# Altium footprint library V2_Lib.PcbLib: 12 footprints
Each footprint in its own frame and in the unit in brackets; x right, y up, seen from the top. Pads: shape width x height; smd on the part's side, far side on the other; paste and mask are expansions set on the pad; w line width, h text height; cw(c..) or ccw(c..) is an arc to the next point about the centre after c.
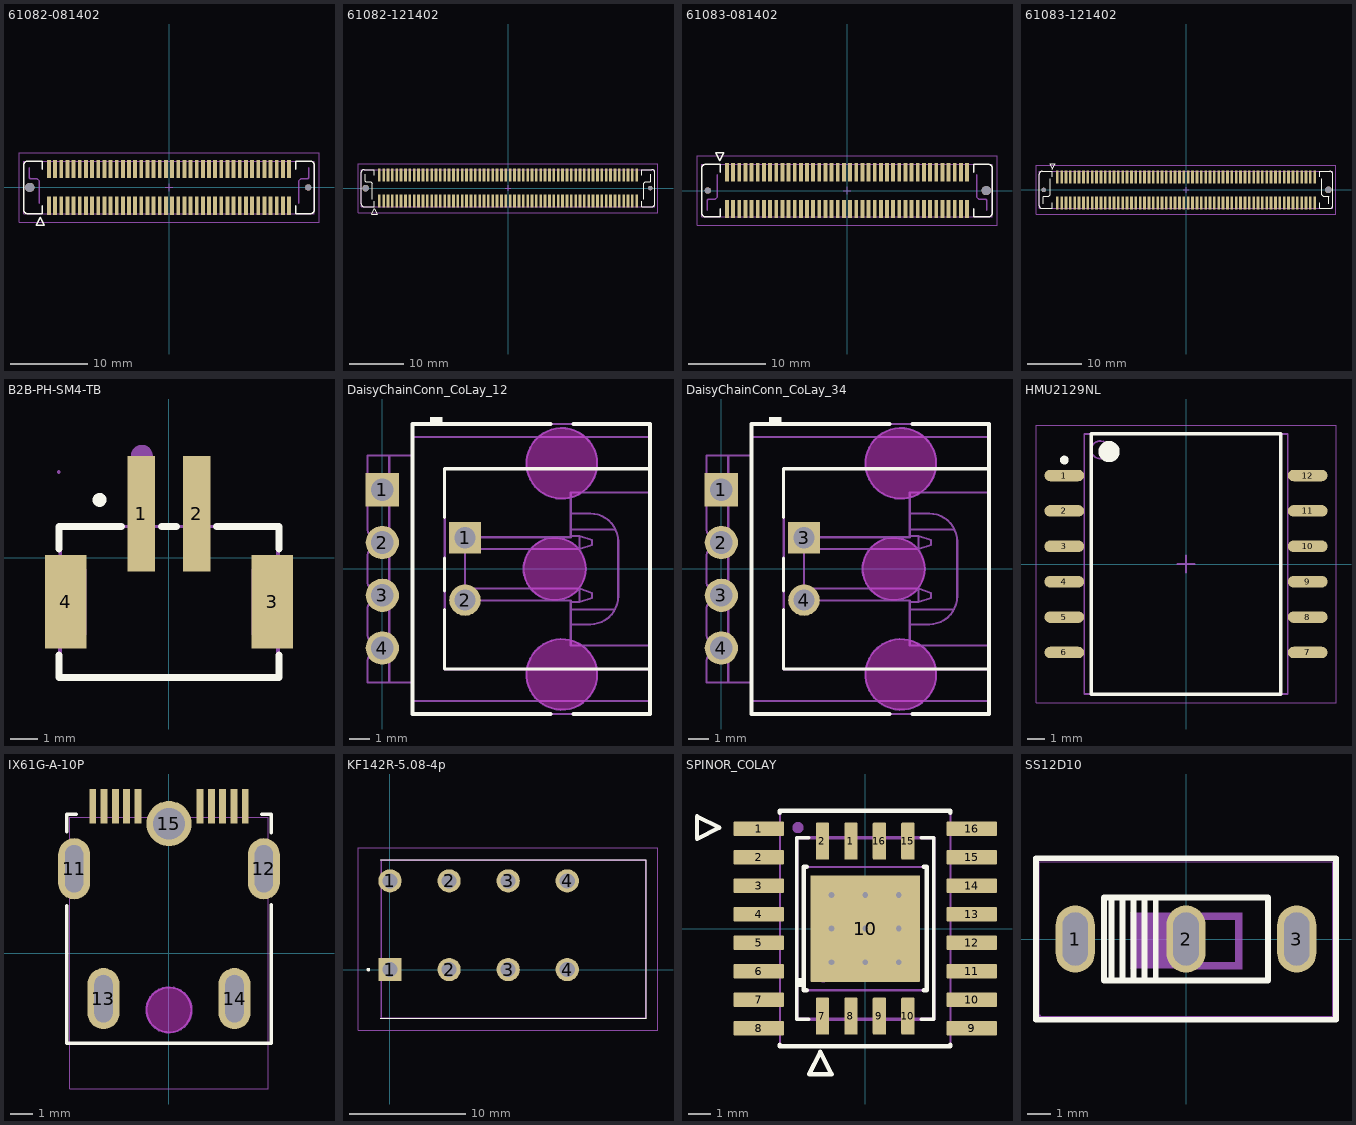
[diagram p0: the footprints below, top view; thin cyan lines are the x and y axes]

## 61082-081402 [mm] "Bergstak 0.8mm Board-to-Board Connector, Receptable, 80 Pos"
height 7.7
pads (82):
  rect 0.5x2.4 smd: 1(-15.6,-2.4) 2(-14.8,-2.4) 3(-14,-2.4) 4(-13.2,-2.4) 5(-12.4,-2.4) 6(-11.6,-2.4) 7(-10.8,-2.4) 8(-10,-2.4) 9(-9.2,-2.4) 10(-8.4,-2.4) 11(-7.6,-2.4) 12(-6.8,-2.4) 13(-6,-2.4) 14(-5.2,-2.4) 15(-4.4,-2.4) 16(-3.6,-2.4) 17(-2.8,-2.4) 18(-2,-2.4) 19(-1.2,-2.4) 20(-0.4,-2.4) 21(0.4,-2.4) 22(1.2,-2.4) 23(2,-2.4) 24(2.8,-2.4) 25(3.6,-2.4) 26(4.4,-2.4) 27(5.2,-2.4) 28(6,-2.4) 29(6.8,-2.4) 30(7.6,-2.4) 31(8.4,-2.4) 32(9.2,-2.4) 33(10,-2.4) 34(10.8,-2.4) 35(11.6,-2.4) 36(12.4,-2.4) 37(13.2,-2.4) 38(14,-2.4) 39(14.8,-2.4) 40(15.6,-2.4) 41(-15.6,2.4) 42(-14.8,2.4) 43(-14,2.4) 44(-13.2,2.4) 45(-12.4,2.4) 46(-11.6,2.4) 47(-10.8,2.4) 48(-10,2.4) 49(-9.2,2.4) 50(-8.4,2.4) 51(-7.6,2.4) 52(-6.8,2.4) 53(-6,2.4) 54(-5.2,2.4) 55(-4.4,2.4) 56(-3.6,2.4) 57(-2.8,2.4) 58(-2,2.4) 59(-1.2,2.4) 60(-0.4,2.4) 61(0.4,2.4) 62(1.2,2.4) 63(2,2.4) 64(2.8,2.4) 65(3.6,2.4) 66(4.4,2.4) 67(5.2,2.4) 68(6,2.4) 69(6.8,2.4) 70(7.6,2.4) 71(8.4,2.4) 72(9.2,2.4) 73(10,2.4) 74(10.8,2.4) 75(11.6,2.4) 76(12.4,2.4) 77(13.2,2.4) 78(14,2.4) 79(14.8,2.4) 80(15.6,2.4)
  round 1.2 hole 1.2: MH1(-18.1,0)
  round 0.8 hole 0.8: MH2(18.1,0)
Top Overlay:
  lines w0.2: -16.5,-2.4 -16.5,-3.4 -18.4,-3.4 cw(c-18.4,-2.9) -18.9,-2.9 -18.9,2.9 cw(c-18.4,2.9) -18.4,3.4 -16.5,3.4 -16.5,2.4 ; 16.5,-2.4 16.5,-3.4 18.4,-3.4 ccw(c18.4,-2.9) 18.9,-2.9 18.9,2.9 ccw(c18.4,2.9) 18.4,3.4 16.5,3.4 16.5,2.4 ; -17.238,-4.905 -16.238,-4.905 -16.738,-3.905 -17.238,-4.905
Mechanical 3:
  lines w0.2: -18.161,2.54 -18.161,1.27 -18.034,1.143 -17.145,1.143 -16.891,0.889 -16.891,-2.032 ; 16.891,-2.032 16.891,0.889 17.145,1.143 18.034,1.143 18.161,1.27 18.161,2.54
Mechanical 5:
  lines w0.1: -18.9,-3.4 -18.9,3.4 18.9,3.4 18.9,-3.4 -18.9,-3.4
Mechanical 15:
  lines w0.05: -19.5,-4.5 -19.5,4.5 19.5,4.5 19.5,-4.5 -19.5,-4.5
  lines w0.1: -0.5,0 0.5,0 ; 0,-0.5 0,0.5
3D body "61082-081402LF--3DModel-STEP-533217.STEP": height 3.7, standoff -0.65, extent -18.9,-3 18.9,3

## 61082-121402 [mm] "Bergstak 0.8mm Board-to-Board Connector, Receptable, 120 Pos, 4.7mm"
height 7.7
pads (122):
  rect 0.5x2.4 smd: 1(-23.6,-2.4) 2(-22.8,-2.4) 3(-22,-2.4) 4(-21.2,-2.4) 5(-20.4,-2.4) 6(-19.6,-2.4) 7(-18.8,-2.4) 8(-18,-2.4) 9(-17.2,-2.4) 10(-16.4,-2.4) 11(-15.6,-2.4) 12(-14.8,-2.4) 13(-14,-2.4) 14(-13.2,-2.4) 15(-12.4,-2.4) 16(-11.6,-2.4) 17(-10.8,-2.4) 18(-10,-2.4) 19(-9.2,-2.4) 20(-8.4,-2.4) 21(-7.6,-2.4) 22(-6.8,-2.4) 23(-6,-2.4) 24(-5.2,-2.4) 25(-4.4,-2.4) 26(-3.6,-2.4) 27(-2.8,-2.4) 28(-2,-2.4) 29(-1.2,-2.4) 30(-0.4,-2.4) 31(0.4,-2.4) 32(1.2,-2.4) 33(2,-2.4) 34(2.8,-2.4) 35(3.6,-2.4) 36(4.4,-2.4) 37(5.2,-2.4) 38(6,-2.4) 39(6.8,-2.4) 40(7.6,-2.4) 41(8.4,-2.4) 42(9.2,-2.4) 43(10,-2.4) 44(10.8,-2.4) 45(11.6,-2.4) 46(12.4,-2.4) 47(13.2,-2.4) 48(14,-2.4) 49(14.8,-2.4) 50(15.6,-2.4) 51(16.4,-2.4) 52(17.2,-2.4) 53(18,-2.4) 54(18.8,-2.4) 55(19.6,-2.4) 56(20.4,-2.4) 57(21.2,-2.4) 58(22,-2.4) 59(22.8,-2.4) 60(23.6,-2.4) 61(-23.6,2.4) 62(-22.8,2.4) 63(-22,2.4) 64(-21.2,2.4) 65(-20.4,2.4) 66(-19.6,2.4) 67(-18.8,2.4) 68(-18,2.4) 69(-17.2,2.4) 70(-16.4,2.4) 71(-15.6,2.4) 72(-14.8,2.4) 73(-14,2.4) 74(-13.2,2.4) 75(-12.4,2.4) 76(-11.6,2.4) 77(-10.8,2.4) 78(-10,2.4) 79(-9.2,2.4) 80(-8.4,2.4) 81(-7.6,2.4) 82(-6.8,2.4) 83(-6,2.4) 84(-5.2,2.4) 85(-4.4,2.4) 86(-3.6,2.4) 87(-2.8,2.4) 88(-2,2.4) 89(-1.2,2.4) 90(-0.4,2.4) 91(0.4,2.4) 92(1.2,2.4) 93(2,2.4) 94(2.8,2.4) 95(3.6,2.4) 96(4.4,2.4) 97(5.2,2.4) 98(6,2.4) 99(6.8,2.4) 100(7.6,2.4) 101(8.4,2.4) 102(9.2,2.4) 103(10,2.4) 104(10.8,2.4) 105(11.6,2.4) 106(12.4,2.4) 107(13.2,2.4) 108(14,2.4) 109(14.8,2.4) 110(15.6,2.4) 111(16.4,2.4) 112(17.2,2.4) 113(18,2.4) 114(18.8,2.4) 115(19.6,2.4) 116(20.4,2.4) 117(21.2,2.4) 118(22,2.4) 119(22.8,2.4) 120(23.6,2.4)
  round 1.2 hole 1.2: MH1(-26.1,0)
  round 0.8 hole 0.8: MH2(26.1,0)
Top Overlay:
  lines w0.2: -26.161,2.54 -26.161,1.27 -26.034,1.143 -25.145,1.143 -24.891,0.889 -24.891,-2.032 ; -24.5,-2.4 -24.5,-3.4 -26.4,-3.4 cw(c-26.4,-2.9) -26.9,-2.9 -26.9,2.9 cw(c-26.4,2.9) -26.4,3.4 -24.5,3.4 -24.5,2.4 ; 24.5,-2.4 24.5,-3.4 26.4,-3.4 ccw(c26.4,-2.9) 26.9,-2.9 26.9,2.9 ccw(c26.4,2.9) 26.4,3.4 24.5,3.4 24.5,2.4 ; 24.891,-2.032 24.891,0.889 25.145,1.143 26.034,1.143 26.161,1.27 26.161,2.54 ; -25.011,-4.826 -24.511,-3.826 -24.011,-4.826 -25.011,-4.826
Mechanical 5:
  lines w0.1: -26.9,-3.4 26.9,-3.4 26.9,3.4 -26.9,3.4 -26.9,-3.4
Mechanical 15:
  lines w0.05: -27.5,-4.5 27.5,-4.5 27.5,4.5 -27.5,4.5 -27.5,-4.5
  lines w0.1: -0.5,0 0.5,0 ; 0,-0.5 0,0.5
3D body "61082-121402LF--3DModel-STEP-533217.STEP": height 3.85, standoff -0.5, extent -26.9,-3 26.9,3

## 61083-081402 [mm] "Bergstak 0.8mm Board-to-Board Connector, Plug, 80 Pos"
height 7.7
pads (82):
  rect 0.5x2.4 smd: 1(-15.6,2.4) 2(-14.8,2.4) 3(-14,2.4) 4(-13.2,2.4) 5(-12.4,2.4) 6(-11.6,2.4) 7(-10.8,2.4) 8(-10,2.4) 9(-9.2,2.4) 10(-8.4,2.4) 11(-7.6,2.4) 12(-6.8,2.4) 13(-6,2.4) 14(-5.2,2.4) 15(-4.4,2.4) 16(-3.6,2.4) 17(-2.8,2.4) 18(-2,2.4) 19(-1.2,2.4) 20(-0.4,2.4) 21(0.4,2.4) 22(1.2,2.4) 23(2,2.4) 24(2.8,2.4) 25(3.6,2.4) 26(4.4,2.4) 27(5.2,2.4) 28(6,2.4) 29(6.8,2.4) 30(7.6,2.4) 31(8.4,2.4) 32(9.2,2.4) 33(10,2.4) 34(10.8,2.4) 35(11.6,2.4) 36(12.4,2.4) 37(13.2,2.4) 38(14,2.4) 39(14.8,2.4) 40(15.6,2.4) 41(-15.6,-2.4) 42(-14.8,-2.4) 43(-14,-2.4) 44(-13.2,-2.4) 45(-12.4,-2.4) 46(-11.6,-2.4) 47(-10.8,-2.4) 48(-10,-2.4) 49(-9.2,-2.4) 50(-8.4,-2.4) 51(-7.6,-2.4) 52(-6.8,-2.4) 53(-6,-2.4) 54(-5.2,-2.4) 55(-4.4,-2.4) 56(-3.6,-2.4) 57(-2.8,-2.4) 58(-2,-2.4) 59(-1.2,-2.4) 60(-0.4,-2.4) 61(0.4,-2.4) 62(1.2,-2.4) 63(2,-2.4) 64(2.8,-2.4) 65(3.6,-2.4) 66(4.4,-2.4) 67(5.2,-2.4) 68(6,-2.4) 69(6.8,-2.4) 70(7.6,-2.4) 71(8.4,-2.4) 72(9.2,-2.4) 73(10,-2.4) 74(10.8,-2.4) 75(11.6,-2.4) 76(12.4,-2.4) 77(13.2,-2.4) 78(14,-2.4) 79(14.8,-2.4) 80(15.6,-2.4)
  round 0.8 hole 0.8: MH1(-18.1,0)
  round 1.2 hole 1.2: MH2(18.1,0)
Top Overlay:
  lines w0.2: -16.5,-2.4 -16.5,-3.4 -18.4,-3.4 cw(c-18.4,-2.9) -18.9,-2.9 -18.9,2.9 cw(c-18.4,2.9) -18.4,3.4 -16.5,3.4 -16.5,2.4 ; 16.5,-2.4 16.5,-3.4 18.4,-3.4 ccw(c18.4,-2.9) 18.9,-2.9 18.9,2.9 ccw(c18.4,2.9) 18.4,3.4 16.5,3.4 16.5,2.4 ; -17.036,4.905 -16.536,3.905 -16.036,4.905 -17.036,4.905
Mechanical 3:
  lines w0.2: -18.161,-2.54 -18.161,-1.27 -18.034,-1.143 -17.145,-1.143 -16.891,-0.889 -16.891,2.032 ; 16.891,2.032 16.891,-0.889 17.145,-1.143 18.034,-1.143 18.161,-1.27 18.161,-2.54
Mechanical 5:
  lines w0.1: -18.9,-3.4 18.9,-3.4 18.9,3.4 -18.9,3.4 -18.9,-3.4
Mechanical 15:
  lines w0.05: -19.5,-4.5 19.5,-4.5 19.5,4.5 -19.5,4.5 -19.5,-4.5
  lines w0.1: -0.5,0 0.5,0 ; 0,-0.5 0,0.5
3D body "61083-081402LF--3DModel-STEP-533217.STEP": height 4.75, standoff -0.6, extent -18.9,-3 18.9,3

## 61083-121402 [mm] "Bergstak 0.8mm Board-to-Board Connector, Plug, 120 Pos, 3.7mm"
height 7.7
pads (122):
  rect 0.5x2.4 smd: 1(-23.6,2.4) 2(-22.8,2.4) 3(-22,2.4) 4(-21.2,2.4) 5(-20.4,2.4) 6(-19.6,2.4) 7(-18.8,2.4) 8(-18,2.4) 9(-17.2,2.4) 10(-16.4,2.4) 11(-15.6,2.4) 12(-14.8,2.4) 13(-14,2.4) 14(-13.2,2.4) 15(-12.4,2.4) 16(-11.6,2.4) 17(-10.8,2.4) 18(-10,2.4) 19(-9.2,2.4) 20(-8.4,2.4) 21(-7.6,2.4) 22(-6.8,2.4) 23(-6,2.4) 24(-5.2,2.4) 25(-4.4,2.4) 26(-3.6,2.4) 27(-2.8,2.4) 28(-2,2.4) 29(-1.2,2.4) 30(-0.4,2.4) 31(0.4,2.4) 32(1.2,2.4) 33(2,2.4) 34(2.8,2.4) 35(3.6,2.4) 36(4.4,2.4) 37(5.2,2.4) 38(6,2.4) 39(6.8,2.4) 40(7.6,2.4) 41(8.4,2.4) 42(9.2,2.4) 43(10,2.4) 44(10.8,2.4) 45(11.6,2.4) 46(12.4,2.4) 47(13.2,2.4) 48(14,2.4) 49(14.8,2.4) 50(15.6,2.4) 51(16.4,2.4) 52(17.2,2.4) 53(18,2.4) 54(18.8,2.4) 55(19.6,2.4) 56(20.4,2.4) 57(21.2,2.4) 58(22,2.4) 59(22.8,2.4) 60(23.6,2.4) 61(-23.6,-2.4) 62(-22.8,-2.4) 63(-22,-2.4) 64(-21.2,-2.4) 65(-20.4,-2.4) 66(-19.6,-2.4) 67(-18.8,-2.4) 68(-18,-2.4) 69(-17.2,-2.4) 70(-16.4,-2.4) 71(-15.6,-2.4) 72(-14.8,-2.4) 73(-14,-2.4) 74(-13.2,-2.4) 75(-12.4,-2.4) 76(-11.6,-2.4) 77(-10.8,-2.4) 78(-10,-2.4) 79(-9.2,-2.4) 80(-8.4,-2.4) 81(-7.6,-2.4) 82(-6.8,-2.4) 83(-6,-2.4) 84(-5.2,-2.4) 85(-4.4,-2.4) 86(-3.6,-2.4) 87(-2.8,-2.4) 88(-2,-2.4) 89(-1.2,-2.4) 90(-0.4,-2.4) 91(0.4,-2.4) 92(1.2,-2.4) 93(2,-2.4) 94(2.8,-2.4) 95(3.6,-2.4) 96(4.4,-2.4) 97(5.2,-2.4) 98(6,-2.4) 99(6.8,-2.4) 100(7.6,-2.4) 101(8.4,-2.4) 102(9.2,-2.4) 103(10,-2.4) 104(10.8,-2.4) 105(11.6,-2.4) 106(12.4,-2.4) 107(13.2,-2.4) 108(14,-2.4) 109(14.8,-2.4) 110(15.6,-2.4) 111(16.4,-2.4) 112(17.2,-2.4) 113(18,-2.4) 114(18.8,-2.4) 115(19.6,-2.4) 116(20.4,-2.4) 117(21.2,-2.4) 118(22,-2.4) 119(22.8,-2.4) 120(23.6,-2.4)
  round 0.8 hole 0.8: MH1(-26.1,0)
  round 1.2 hole 1.2: MH2(26.1,0)
Top Overlay:
  lines w0.2: -26.161,-2.54 -26.161,-1.27 -26.034,-1.143 -25.145,-1.143 -24.891,-0.889 -24.891,2.032 ; -24.5,-2.4 -24.5,-3.4 -26.4,-3.4 cw(c-26.4,-2.9) -26.9,-2.9 -26.9,2.9 cw(c-26.4,2.9) -26.4,3.4 -24.5,3.4 -24.5,2.4 ; 24.5,-2.4 24.5,-3.4 26.4,-3.4 ccw(c26.4,-2.9) 26.9,-2.9 26.9,2.9 ccw(c26.4,2.9) 26.4,3.4 24.5,3.4 24.5,2.4 ; 24.891,2.032 24.891,-0.889 25.145,-1.143 26.034,-1.143 26.161,-1.27 26.161,-2.54 ; -25.011,4.826 -24.011,4.826 -24.511,3.826 -25.011,4.826
Mechanical 5:
  lines w0.1: -26.9,-3.4 -26.9,3.4 26.9,3.4 26.9,-3.4 -26.9,-3.4
Mechanical 15:
  lines w0.05: -27.5,-4.5 -27.5,4.5 27.5,4.5 27.5,-4.5 -27.5,-4.5
  lines w0.1: -0.5,0 0.5,0 ; 0,-0.5 0,0.5
3D body "61083-121402LF--3DModel-STEP-533217.STEP": height 4.85, standoff -0.5, extent -26.9,-3 26.9,3

## B2B-PH-SM4-TB [mm]
pads (4):
  rect 1x4.2 smd paste+0 mask+0.05: 1(-1,1.6) 2(1,1.6)
  rect 1.5x3.4 smd paste+0 mask+0.05: 3(3.75,-1.6) 4(-3.75,-1.6)
Top Overlay:
  circle w0.254: c-2.524,2.108 r0.127
  lines w0.254: -4,-3.531 -4,-4.35 4,-4.35 4,-3.531 ; -4,0.331 -4,1.15 -1.731,1.15 ; -0.269,1.15 0.269,1.15 ; 1.731,1.15 4,1.15 4,0.331
Mechanical 5:
  lines w0.1: -3.937,-4.318 -3.937,1.143 3.937,1.143 3.937,-4.318 -3.937,-4.318
Mechanical 6:
  circle w0.4: c-0.989,3.708 r0.2
Mechanical 15:
  region: -3.943,3.126 -3.943,3.151 -3.979,3.186 -4.028,3.186 -4.063,3.151 -4.063,3.126 -4.063,3.101 -4.028,3.066 -3.979,3.066 -3.943,3.101
  region: -1.25,3.126 -0.75,3.126 -0.75,-0.074 -1.25,-0.074
  region: 0.75,3.126 1.25,3.126 1.25,-0.074 0.75,-0.074
  region: -4.003,-0.4 -3.003,-0.4 -3.003,-2.8 -4.003,-2.8
  region: 3.003,-0.4 4.003,-0.4 4.003,-2.8 3.003,-2.8
  lines w0.051: -4.003,-4.338 4.003,-4.338 4.003,1.161 -3.987,1.161 -4.003,-2.462 -4.003,-4.338
3D body "User Library-JST_B2B-PH-SM4-TB-white.STEP": height 6.6, standoff 0, extent -3.975,-4.318 3.975,2.682

## DaisyChainConn_CoLay_12 [mm] "Header(shrouded), 2.54mm, 4x1, R/A, TH"
height 7.12
pads (6):
  rect 1.6x1.6 hole 1.09: 1(0,3.81)
  rect 1.52x1.52 hole 1.02 mask+0.076: 1(3.98,1.5)
  round 1.6 hole 1.09: 2(0,1.27) 3(0,-1.27) 4(0,-3.81)
  round 1.52 hole 1.02 mask+0.076: 2(3.98,-1.5)
Top Overlay:
  region: 2.9,7 2.9,7.316 2.3,7.316 2.3,7
  lines w0.152: 3,-1.948 3,-4.825 12.9,-4.825 12.9,4.825 3,4.825 3,2.489 ; 3,-1.052 3,0.511
  lines w0.2: 8.1,-6.984 1.45,-6.984 1.45,-6.354 1.45,6.354 1.45,6.984 8.1,6.984 ; 9.2,-6.984 12.88,-6.984 12.88,-6.354 12.88,-3.683 12.88,3.683 12.88,6.354 12.88,6.984 9.2,6.984
Keep-Out Layer:
  board cut-out: 8.3,1.5 8.448,1.5 8.738,1.442 9.011,1.329 9.256,1.165 9.465,0.956 9.629,0.711 9.742,0.438 9.8,0.148 9.8,0 9.8,-0.148 9.742,-0.438 9.629,-0.711 9.465,-0.956 9.256,-1.165 9.011,-1.329 8.738,-1.442 8.448,-1.5 8.3,-1.5 8.152,-1.5 7.862,-1.442 7.589,-1.329 7.344,-1.165 7.135,-0.956 6.971,-0.711 6.858,-0.438 6.8,-0.148 6.8,0 6.8,0.148 6.858,0.438 6.971,0.711 7.135,0.956 7.344,1.165 7.589,1.329 7.862,1.442 8.152,1.5
  board cut-out: 8.64,-3.38 8.807,-3.38 9.136,-3.445 9.445,-3.573 9.724,-3.76 9.96,-3.996 10.147,-4.275 10.275,-4.584 10.34,-4.913 10.34,-5.08 10.34,-5.247 10.275,-5.576 10.147,-5.885 9.96,-6.164 9.724,-6.4 9.445,-6.587 9.136,-6.715 8.807,-6.78 8.64,-6.78 8.473,-6.78 8.144,-6.715 7.835,-6.587 7.556,-6.4 7.32,-6.164 7.133,-5.885 7.005,-5.576 6.94,-5.247 6.94,-5.08 6.94,-4.913 7.005,-4.584 7.133,-4.275 7.32,-3.996 7.556,-3.76 7.835,-3.573 8.144,-3.445 8.473,-3.38
  board cut-out: 8.64,6.78 8.807,6.78 9.136,6.715 9.445,6.587 9.724,6.4 9.96,6.164 10.147,5.885 10.275,5.576 10.34,5.247 10.34,5.08 10.34,4.913 10.275,4.584 10.147,4.275 9.96,3.996 9.724,3.76 9.445,3.573 9.136,3.445 8.807,3.38 8.64,3.38 8.473,3.38 8.144,3.445 7.835,3.573 7.556,3.76 7.32,3.996 7.133,4.275 7.005,4.584 6.94,4.913 6.94,5.08 6.94,5.247 7.005,5.576 7.133,5.885 7.32,6.164 7.556,6.4 7.835,6.587 8.144,6.715 8.473,6.78
Mechanical 1:
  circle w0.1: c8.3,0 r1.5
  circle w0.1: c8.64,-5.08 r1.7
  circle w0.1: c8.64,5.08 r1.7
Mechanical 5:
  lines w0.1: -0.33,-4.13 -0.33,-3.49 ; -0.33,-1.59 -0.33,-0.95 ; -0.33,0.95 -0.33,1.59 ; -0.33,3.49 -0.33,4.13 ; 0.332,-4.13 -0.409,-4.13 ccw(c-0.409,-4.43) -0.709,-4.43 -0.709,-5.461 0.332,-5.461 ; 0.332,-3.49 -0.409,-3.49 cw(c-0.409,-3.19) -0.709,-3.19 -0.709,-1.89 cw(c-0.409,-1.89) -0.409,-1.59 0.332,-1.59 ; 0.332,-0.95 -0.409,-0.95 cw(c-0.409,-0.65) -0.709,-0.65 -0.709,0.65 cw(c-0.409,0.65) -0.409,0.95 0.332,0.95 ; 0.332,1.59 -0.409,1.59 cw(c-0.409,1.89) -0.709,1.89 -0.709,3.19 cw(c-0.409,3.19) -0.409,3.49 0.332,3.49 ; 0.332,4.13 -0.409,4.13 cw(c-0.409,4.43) -0.709,4.43 -0.709,5.461 0.332,5.461 ; 1.45,-5.461 0.332,-5.461 ; 1.45,5.461 0.332,5.461 ; 3.99,-0.95 9.486,-0.95 ; 3.99,0.95 9.486,0.95 ; 9.07,-1.949 11.201,-1.949 ; 9.07,-1.59 9.486,-1.59 ; 9.07,1.59 9.486,1.59 ; 9.07,1.905 11.223,1.905 ; 0.332,-5.461 0.332,5.461 ; 1.45,-6.354 12.88,-6.354 ; 1.45,-6.354 1.45,6.354 ; 1.45,-6.354 1.45,-6.984 12.88,-6.984 12.88,-6.354 ; 1.45,6.354 1.45,6.984 12.88,6.984 12.88,6.354 ; 1.45,6.354 12.88,6.354 ; 9.07,-2.667 9.07,-1.524 3.99,-1.524 3.99,1.524 9.07,1.524 9.07,2.667 ; 9.07,-2.667 10.01,-2.667 ccw(c10.01,-1.321) 11.356,-1.321 11.356,1.321 ccw(c10.01,1.321) 10.01,2.667 9.07,2.667 ; 9.07,-2.667 9.07,-3.683 12.88,-3.683 ; 9.07,2.667 9.07,3.683 12.88,3.683 ; 9.486,-1.59 9.486,-0.95 ; 9.486,-1.59 10.086,-1.39 10.086,-1.15 9.486,-0.95 ; 9.486,0.95 9.486,1.59 ; 9.486,0.95 10.086,1.15 10.086,1.39 9.486,1.59 ; 12.88,-6.354 12.88,-3.683 ; 12.88,-3.683 12.88,3.683 ; 12.88,3.683 12.88,6.354
  lines w0.127: 3,-4.825 3,4.825 12.9,4.825 12.9,-4.825 3,-4.825
  text ".Designator" at 2.97,-4.3 h1.02
3D body: height 0.25, standoff 0, extent 3.726,1.5 3.98,1.754
3D body "705510038.stp": height 6.6, standoff -4.19, extent -0.709,-6.984 12.88,6.984

## DaisyChainConn_CoLay_34 [mm] "Header(shrouded), 2.54mm, 4x1, R/A, TH"
height 7.12
pads (6):
  rect 1.6x1.6 hole 1.09: 1(0,3.81)
  round 1.6 hole 1.09: 2(0,1.27) 3(0,-1.27) 4(0,-3.81)
  rect 1.52x1.52 hole 1.02 mask+0.076: 3(3.98,1.5)
  round 1.52 hole 1.02 mask+0.076: 4(3.98,-1.5)
Top Overlay:
  region: 2.9,7 2.9,7.316 2.3,7.316 2.3,7
  lines w0.152: 3,-1.948 3,-4.825 12.9,-4.825 12.9,4.825 3,4.825 3,2.489 ; 3,-1.052 3,0.511
  lines w0.2: 8.1,-6.984 1.45,-6.984 1.45,-6.354 1.45,6.354 1.45,6.984 8.1,6.984 ; 9.2,-6.984 12.88,-6.984 12.88,-6.354 12.88,-3.683 12.88,3.683 12.88,6.354 12.88,6.984 9.2,6.984
Keep-Out Layer:
  board cut-out: 8.64,6.78 8.807,6.78 9.136,6.715 9.445,6.587 9.724,6.4 9.96,6.164 10.147,5.885 10.275,5.576 10.34,5.247 10.34,5.08 10.34,4.913 10.275,4.584 10.147,4.275 9.96,3.996 9.724,3.76 9.445,3.573 9.136,3.445 8.807,3.38 8.64,3.38 8.473,3.38 8.144,3.445 7.835,3.573 7.556,3.76 7.32,3.996 7.133,4.275 7.005,4.584 6.94,4.913 6.94,5.08 6.94,5.247 7.005,5.576 7.133,5.885 7.32,6.164 7.556,6.4 7.835,6.587 8.144,6.715 8.473,6.78
  board cut-out: 8.64,-3.38 8.807,-3.38 9.136,-3.445 9.445,-3.573 9.724,-3.76 9.96,-3.996 10.147,-4.275 10.275,-4.584 10.34,-4.913 10.34,-5.08 10.34,-5.247 10.275,-5.576 10.147,-5.885 9.96,-6.164 9.724,-6.4 9.445,-6.587 9.136,-6.715 8.807,-6.78 8.64,-6.78 8.473,-6.78 8.144,-6.715 7.835,-6.587 7.556,-6.4 7.32,-6.164 7.133,-5.885 7.005,-5.576 6.94,-5.247 6.94,-5.08 6.94,-4.913 7.005,-4.584 7.133,-4.275 7.32,-3.996 7.556,-3.76 7.835,-3.573 8.144,-3.445 8.473,-3.38
  board cut-out: 8.3,1.5 8.448,1.5 8.738,1.442 9.011,1.329 9.256,1.165 9.465,0.956 9.629,0.711 9.742,0.438 9.8,0.148 9.8,0 9.8,-0.148 9.742,-0.438 9.629,-0.711 9.465,-0.956 9.256,-1.165 9.011,-1.329 8.738,-1.442 8.448,-1.5 8.3,-1.5 8.152,-1.5 7.862,-1.442 7.589,-1.329 7.344,-1.165 7.135,-0.956 6.971,-0.711 6.858,-0.438 6.8,-0.148 6.8,0 6.8,0.148 6.858,0.438 6.971,0.711 7.135,0.956 7.344,1.165 7.589,1.329 7.862,1.442 8.152,1.5
Mechanical 1:
  circle w0.1: c8.64,5.08 r1.7
  circle w0.1: c8.64,-5.08 r1.7
  circle w0.1: c8.3,0 r1.5
Mechanical 5:
  lines w0.1: -0.33,-4.13 -0.33,-3.49 ; -0.33,-1.59 -0.33,-0.95 ; -0.33,0.95 -0.33,1.59 ; -0.33,3.49 -0.33,4.13 ; 0.332,-4.13 -0.409,-4.13 ccw(c-0.409,-4.43) -0.709,-4.43 -0.709,-5.461 0.332,-5.461 ; 0.332,-3.49 -0.409,-3.49 cw(c-0.409,-3.19) -0.709,-3.19 -0.709,-1.89 cw(c-0.409,-1.89) -0.409,-1.59 0.332,-1.59 ; 0.332,-0.95 -0.409,-0.95 cw(c-0.409,-0.65) -0.709,-0.65 -0.709,0.65 cw(c-0.409,0.65) -0.409,0.95 0.332,0.95 ; 0.332,1.59 -0.409,1.59 cw(c-0.409,1.89) -0.709,1.89 -0.709,3.19 cw(c-0.409,3.19) -0.409,3.49 0.332,3.49 ; 0.332,4.13 -0.409,4.13 cw(c-0.409,4.43) -0.709,4.43 -0.709,5.461 0.332,5.461 ; 1.45,-5.461 0.332,-5.461 ; 1.45,5.461 0.332,5.461 ; 3.99,-0.95 9.486,-0.95 ; 3.99,0.95 9.486,0.95 ; 9.07,-1.949 11.201,-1.949 ; 9.07,-1.59 9.486,-1.59 ; 9.07,1.59 9.486,1.59 ; 9.07,1.905 11.223,1.905 ; 0.332,-5.461 0.332,5.461 ; 1.45,-6.354 1.45,-6.984 12.88,-6.984 12.88,-6.354 ; 1.45,-6.354 1.45,6.354 ; 1.45,-6.354 12.88,-6.354 ; 1.45,6.354 12.88,6.354 ; 1.45,6.354 1.45,6.984 12.88,6.984 12.88,6.354 ; 9.07,-2.667 9.07,-3.683 12.88,-3.683 ; 9.07,-2.667 10.01,-2.667 ccw(c10.01,-1.321) 11.356,-1.321 11.356,1.321 ccw(c10.01,1.321) 10.01,2.667 9.07,2.667 ; 9.07,-2.667 9.07,-1.524 3.99,-1.524 3.99,1.524 9.07,1.524 9.07,2.667 ; 9.07,2.667 9.07,3.683 12.88,3.683 ; 9.486,-1.59 10.086,-1.39 10.086,-1.15 9.486,-0.95 ; 9.486,-1.59 9.486,-0.95 ; 9.486,0.95 10.086,1.15 10.086,1.39 9.486,1.59 ; 9.486,0.95 9.486,1.59 ; 12.88,-6.354 12.88,-3.683 ; 12.88,-3.683 12.88,3.683 ; 12.88,3.683 12.88,6.354
  text ".Designator" at 2.97,-4.3 h1.02
Mechanical 13:
  lines w0.127: 3,-4.825 12.9,-4.825 12.9,4.825 3,4.825 3,-4.825
3D body: height 0.25, standoff 0, extent 3.726,1.5 3.98,1.754
3D body "705510038.stp": height 6.6, standoff -4.19, extent -0.709,-6.984 12.88,6.984

## HMU2129NL [mm] "SOP, 12-Leads, Body 14.65x11.50mm, Pitch 2.00mm, IPC Low Density"
height 5.5
pads (12):
  oval 2.25x0.65 smd: 1(-6.875,5) 2(-6.875,3) 3(-6.875,1) 4(-6.875,-1) 5(-6.875,-3) 6(-6.875,-5) 7(6.875,-5) 8(6.875,-3) 9(6.875,-1) 10(6.875,1) 11(6.875,3) 12(6.875,5)
Top Overlay:
  circle w0.6: c-4.35,6.35 r0.3
  circle w0.25: c-6.875,5.875 r0.125
  lines w0.2: -5.35,-7.35 5.35,-7.35 5.35,7.35 -5.35,7.35 -5.35,-7.35
Mechanical 13:
  circle w0.1: c-4.85,6.45 r0.5
  lines w0.1: -5.75,-7.35 5.75,-7.35 5.75,7.35 -5.75,7.35 -5.75,-7.35
Mechanical 15:
  lines w0.05: -8.475,-7.85 8.475,-7.85 8.475,7.85 -8.475,7.85 -8.475,-7.85
  lines w0.1: -0.5,0 0.5,0 ; 0,-0.5 0,0.5

## IX61G-A-10P [mm]
pads (15):
  rect 0.305x1.524 smd paste+0 mask+0.05: 1(-3.375,6.5) 2(-2.875,6.5) 3(-2.375,6.5) 4(-1.875,6.5) 5(-1.375,6.5) 6(1.375,6.5) 7(1.875,6.5) 8(2.375,6.5) 9(2.875,6.5) 10(3.375,6.5)
  oval 1.408x2.708 hole 0.8 slot 2.1 at 90 deg paste-1.354 mask+0: 11(-4.2,3.73) 12(4.2,3.73) 13(-2.9,-2.02) 14(2.9,-2.02)
  round 2 hole 1.4 paste-1.354 mask+0: 15(0,5.73)
Top Overlay:
  lines w0.152: -4.521,2.094 -4.521,-4 4.521,-4 4.521,2.144 ; -4.521,5.366 -4.521,6.147 -4.11,6.147 ; 4.11,6.147 4.521,6.147 4.521,5.316
Keep-Out Layer:
  board cut-out: 0,-1.52 0.098,-1.52 0.292,-1.559 0.474,-1.634 0.637,-1.743 0.777,-1.883 0.886,-2.047 0.962,-2.229 1,-2.422 1,-2.52 1,-2.619 0.962,-2.812 0.886,-2.994 0.777,-3.158 0.637,-3.297 0.474,-3.406 0.292,-3.482 0.098,-3.52 0,-3.52 -0.098,-3.52 -0.292,-3.482 -0.474,-3.406 -0.637,-3.297 -0.777,-3.158 -0.886,-2.994 -0.962,-2.812 -1,-2.619 -1,-2.52 -1,-2.422 -0.962,-2.229 -0.886,-2.047 -0.777,-1.883 -0.637,-1.743 -0.474,-1.634 -0.292,-1.559 -0.098,-1.52
Mechanical 1:
  circle w0.1: c0,-2.52 r1
Mechanical 5:
  lines w0.025: -4.394,-6.02 4.394,-6.02 4.394,6.02 -4.394,6.02 -4.394,-6.02
3D body "IX61G-A-10P.stp": height 9.75, standoff -1.5, extent -4.4,-6 4.4,6.8

## KF142R-5.08-4p [mm]
pads (8):
  rect 2x2 hole 1.3: 1(0,0)
  round 2 hole 1.3: 1(0,7.62) 2(5.08,0) 2(5.08,7.62) 3(10.16,0) 3(10.16,7.62) 4(15.24,0) 4(15.24,7.62)
Top Overlay:
  circle w0.2: c-1.85,0 r0.05
  lines w0.1: -0.82,-4.2 22.04,-4.2 22.04,9.45 -0.82,9.45
Mechanical 5:
  lines w0.127: -0.762,-4.191 -0.762,9.398 21.971,9.398 21.971,-4.191 -0.762,-4.191
Mechanical 20:
  lines w0.05: -2.75,-5.2 -2.75,10.45 23.04,10.45 23.04,-5.2 -2.75,-5.2
3D body "pxc_1791282_03_FFKDSA1-H1-5-08-4_3D.stp": height 12.7, standoff -3.4, extent -0.762,-4.202 22.098,9.398

## SPINOR_COLAY [mm]
pads (25):
  rrect15% 2.25x0.65 smd: 1(-4.75,4.445) 2(-4.75,3.175) 3(-4.75,1.905) 4(-4.75,0.635) 5(-4.75,-0.635) 6(-4.75,-1.905) 7(-4.75,-3.175) 8(-4.75,-4.445) 9(4.75,-4.445) 10(4.75,-3.175) 11(4.75,-1.905) 12(4.75,-0.635) 13(4.75,0.635) 14(4.75,1.905) 15(4.75,3.175) 16(4.75,4.445)
  rrect17% 0.6x1.65 smd: 1(-0.635,3.9) 2(-1.905,3.9) 7(-1.905,-3.9) 8(-0.635,-3.9) 9(0.635,-3.9) 10(1.905,-3.9) 15(1.905,3.9) 16(0.635,3.9)
  rrect2% 4.9x4.75 smd paste+0 mask+0: 10(0,0)
via -1.5,1.5 diameter 0.508 hole 0.254
via 1.5,1.5 diameter 0.508 hole 0.254
via 1.5,-1.5 diameter 0.508 hole 0.254
via -1.5,-1.5 diameter 0.508 hole 0.254
via 0,-1.5 diameter 0.508 hole 0.254
via 0,1.5 diameter 0.508 hole 0.254
via 1.5,0 diameter 0.508 hole 0.254
via -1.5,0 diameter 0.508 hole 0.254
via 0,0 diameter 0.508 hole 0.254
Top Overlay:
  region: -2.8,-2.6 -2.8,-2.2 -3,-2.2 -3,-2.6
  lines w0.15: -2.505,-4.05 -3.05,-4.05 -3.05,4.05 -2.505,4.05 ; 2.505,-4.05 3.05,-4.05 3.05,4.05 2.505,4.05
  lines w0.2: -3.8,-5.17 -3.8,-5.25 3.8,-5.25 3.8,-5.17 ; -3.8,5.17 -3.8,5.25 3.8,5.25 3.8,5.17 ; -2.605,-2.75 -2.75,-2.75 -2.75,2.75 -2.605,2.75 ; 2.605,-2.75 2.75,-2.75 2.75,2.75 2.605,2.75 ; -7.5,4 -6.5,4.5 -7.5,5 -7.5,4 ; -2.5,-6.5 -2,-5.5 -1.5,-6.5 -2.5,-6.5
Mechanical 5:
  circle w0.1: c-1.85,-1.85 r0.5
  circle w0.25: c-3,4.5 r0.125
  lines w0.1: -3.8,-4.6 -5.325,-4.6 -5.325,-4.29 -3.8,-4.29 ; -3.8,-3.33 -5.325,-3.33 -5.325,-3.02 -3.8,-3.02 ; -3.8,-2.06 -5.325,-2.06 -5.325,-1.75 -3.8,-1.75 ; -3.8,-0.79 -5.325,-0.79 -5.325,-0.48 -3.8,-0.48 ; -3.8,0.48 -5.325,0.48 -5.325,0.79 -3.8,0.79 ; -3.8,1.75 -5.325,1.75 -5.325,2.06 -3.8,2.06 ; -3.8,3.02 -5.325,3.02 -5.325,3.33 -3.8,3.33 ; -3.8,4.29 -5.325,4.29 -5.325,4.6 -3.8,4.6 ; 3.8,-4.6 5.325,-4.6 5.325,-4.29 3.8,-4.29 ; 3.8,-3.33 5.325,-3.33 5.325,-3.02 3.8,-3.02 ; 3.8,-2.06 5.325,-2.06 5.325,-1.75 3.8,-1.75 ; 3.8,-0.79 5.325,-0.79 5.325,-0.48 3.8,-0.48 ; 3.8,0.48 5.325,0.48 5.325,0.79 3.8,0.79 ; 3.8,1.75 5.325,1.75 5.325,2.06 3.8,2.06 ; 3.8,3.02 5.325,3.02 5.325,3.33 3.8,3.33 ; 3.8,4.29 5.325,4.29 5.325,4.6 3.8,4.6 ; -3.8,-5.25 3.8,-5.25 3.8,5.25 -3.8,5.25 -3.8,-5.25 ; -2.75,-2.75 2.75,-2.75 2.75,2.75 -2.75,2.75 -2.75,-2.75
  lines w0.15: -3.05,-4.05 3.05,-4.05 3.05,4.05 -3.05,4.05 -3.05,-4.05
  text ".Designator" at -3.5,-0.2 h0.7
3D body "IC_S25FL128SAGNFI000_WSON8.STEP": height 0.25, standoff 0, extent -3.226,-4.475 3.226,4.475

## SS12D10 [mm]
pads (3):
  oval 1.7x2.9 hole 1.1 slot 2.3 at 90 deg paste+0 mask+0.05: 1(-4.8,0) 2(0,0) 3(4.8,0)
Top Overlay:
  lines w0.254: -3.242,-1.8 -3.233,-1.8 -3.233,1.8 ; -2.762,-1.8 -2.753,-1.8 -2.753,1.8 ; -2.283,-1.8 -2.273,-1.8 -2.273,1.8 ; -1.803,-1.8 -1.793,-1.8 -1.793,1.8 ; -1.314,1.8 -1.314,-1.8 -1.257,-1.8 ; 2.317,1.8 2.74,1.8 ; 2.45,1.8 -3.55,1.8 -3.55,-1.8 3.55,-1.8 3.55,1.3 3.55,1.8 2.55,1.8 ; -6.5,-3.5 -6.5,3.5 6.5,3.5 6.5,-3.5 -6.5,-3.5
Mechanical 5:
  lines w0.1: -6.5,-3.5 6.5,-3.5 6.5,3.5 -6.5,3.5 -6.5,-3.5
Mechanical 6:
  region: -2.4,1.13 0,1.13 0,-1.27 -2.4,-1.27
  region: -0.013,1.129 2.387,1.129 2.425,1.129 2.425,0.826 -0.015,0.826 -0.015,0.926
  region: 2.124,-1.311 2.124,1.089 2.124,1.127 2.428,1.127 2.428,-1.313 2.327,-1.313
  region: -0.021,-1.007 2.379,-1.007 2.417,-1.007 2.417,-1.311 -0.023,-1.311 -0.023,-1.21
  region: -0.019,-1.301 -0.019,1.099 -0.019,1.137 0.284,1.137 0.284,-1.303 0.184,-1.303
Mechanical 15:
  region: -6.29,-3.35 -6.29,-3.325 -6.325,-3.29 -6.375,-3.29 -6.41,-3.325 -6.41,-3.35 -6.41,-3.375 -6.375,-3.41 -6.325,-3.41 -6.29,-3.375
  region: -5.2,0.65 -4.4,0.65 -4.4,-0.65 -5.2,-0.65
  region: -0.4,0.65 0.4,0.65 0.4,-0.65 -0.4,-0.65
  region: 4.4,0.65 5.2,0.65 5.2,-0.65 4.4,-0.65
  lines w0.051: -6.35,-3.35 -6.35,3.35 6.35,3.35 6.35,-3.35 -6.35,-3.35
3D body "12d10l10.step": height 16.4, standoff -6.9, extent -6.5,-3.4 6.5,3.4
